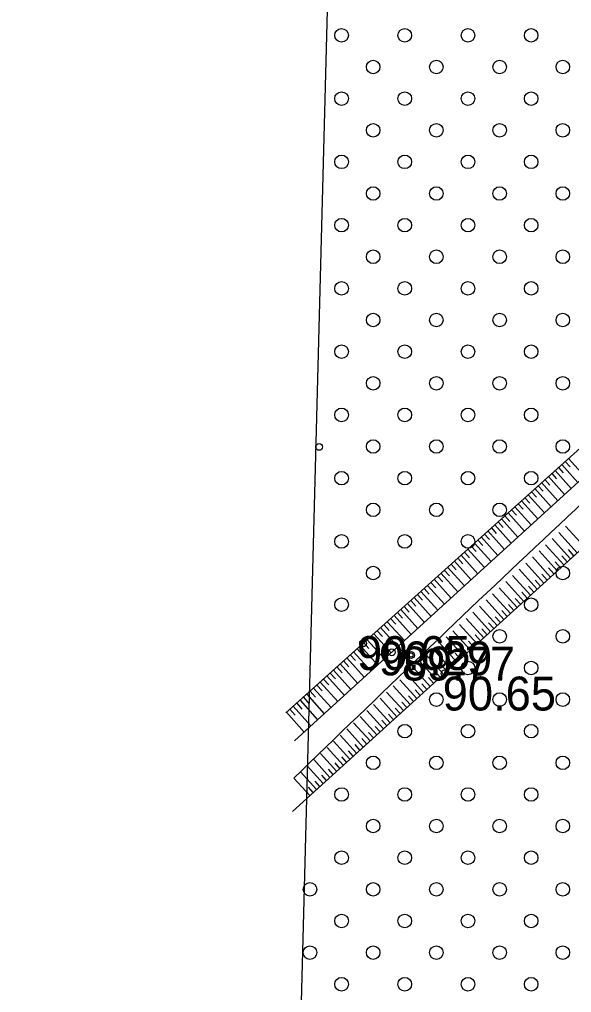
# Model space of a CAD drawing. Extents: x 316000 to 728450, y 314368 to 726000.
# Drawn here: x 725524.8 to 725586, y 315450.6 to 315558.3 of the extents above; entities that cross this region are included whole.
import ezdxf

# ---------------------------------------------------------------- set-up
doc = ezdxf.new("R2010")
doc.units = 0
for name, color, linetype in [('HIDG_ELEM_####_####_#', 7, 'Continuous'), ('HIDG_GRAV_####_####_#', 7, 'Continuous'), ('RAMI_UZMR_####_####_#', 7, 'Continuous'), ('RELJ_AATZ_####_TKST_#', 7, 'Continuous'), ('RELJ_ELEM_####_####_#', 7, 'Continuous'), ('RELJ_NOGA_####_####_#', 7, 'Continuous'), ('TERT_ELEM_####_####_#', 7, 'Continuous')]:
    doc.layers.add(name, color=color, linetype=linetype)

msp = doc.modelspace()

# ---------------------------------------------------------------- linework, layer by layer
at = {"layer": 'HIDG_ELEM_####_####_#'}
msp.add_circle((725568.19, 315487.93), 0.225, dxfattribs=at)
at = {"layer": 'HIDG_GRAV_####_####_#'}
msp.add_line((725611.33, 315529.51), (725555.29, 315478.43), dxfattribs=at)
msp.add_spline([(725741.16, 315628.11), (725732.01, 315633.48), (725729.37, 315630.94), (725612.67, 315527.51), (725555.21, 315474.31)], degree=3, dxfattribs=at)
at = {"layer": 'RAMI_UZMR_####_####_#'}
msp.add_lwpolyline([(727254.69, 315085.95), (727002.7, 315002.84), (726508.21, 314868.03), (726416.7, 314837.05), (725982.38, 314530.96), (725916.44, 314513.26), (725799.16, 314549.2), (725735.9, 314623.63), (725701.82, 314711.1), (725697.25, 315112.64), (725659.91, 315163.35), (725614.81, 315211.65), (725561.8, 315231.45), (725500.09, 315274.21), (725474.77, 315308.26), (725484.26, 315374.77), (725505.03, 315405.04), (725554.87, 315404.25), (725559.14, 315567.14), (725558.67, 315591.68), (725662, 315676.73), (726089.69, 315915.19)], dxfattribs=at)
at = {"layer": 'RELJ_ELEM_####_####_#'}
for centre in [(725558.01, 315510.96), (725562.88, 315489.21), (725566.06, 315488.23), (725568.19, 315487.93), (725571.91, 315485.9)]:
    msp.add_circle(centre, 0.375, dxfattribs=at)
at = {"layer": 'RELJ_NOGA_####_####_#'}
for p, q in [((725610.17, 315531.75), (725554.34, 315481.53)), ((725614.75, 315524.79), (725555.07, 315470.62)), ((725585.26, 315509.35), (725585.8, 315508.75)), ((725585.64, 315509.68), (725587.41, 315507.71)), ((725584.15, 315508.34), (725585.94, 315506.36)), ((725584.52, 315508.68), (725585.06, 315508.08)), ((725584.89, 315509.01), (725586.67, 315507.03)), ((725582.66, 315507.01), (725584.46, 315505.01)), ((725583.03, 315507.34), (725583.57, 315506.74)), ((725583.4, 315507.68), (725585.2, 315505.68)), ((725583.78, 315508.01), (725584.31, 315507.41)), ((725581.55, 315506), (725582.09, 315505.4)), ((725581.92, 315506.34), (725583.72, 315504.34)), ((725582.29, 315506.67), (725582.83, 315506.07)), ((725580.43, 315505), (725582.24, 315502.99)), ((725580.8, 315505.33), (725581.34, 315504.73)), ((725581.17, 315505.67), (725582.98, 315503.66)), ((725579.32, 315504), (725579.86, 315503.39)), ((725579.69, 315504.33), (725581.5, 315502.32)), ((725580.06, 315504.67), (725580.6, 315504.06)), ((725577.83, 315502.66), (725578.38, 315502.05)), ((725578.2, 315502.99), (725580.02, 315500.97)), ((725578.57, 315503.33), (725579.12, 315502.72)), ((725578.94, 315503.66), (725580.76, 315501.64)), ((725576.71, 315501.66), (725578.54, 315499.62)), ((725577.09, 315501.99), (725577.63, 315501.38)), ((725577.46, 315502.33), (725579.28, 315500.3)), ((725587.35, 315499.92), (725585.31, 315502.17)), ((725575.6, 315500.65), (725576.15, 315500.04)), ((725575.97, 315500.99), (725577.81, 315498.95)), ((725576.34, 315501.32), (725576.89, 315500.71)), ((725585.87, 315498.58), (725583.84, 315500.81)), ((725586.61, 315499.25), (725584.57, 315501.49)), ((725574.48, 315499.65), (725576.33, 315497.6)), ((725574.86, 315499.98), (725575.41, 315499.37)), ((725575.23, 315500.32), (725577.07, 315498.27)), ((725584.39, 315497.23), (725582.37, 315499.45)), ((725585.13, 315497.91), (725583.1, 315500.13)), ((725586.24, 315498.91), (725585.63, 315499.59)), ((725573.37, 315498.65), (725573.92, 315498.03)), ((725573.74, 315498.98), (725575.59, 315496.93)), ((725574.11, 315499.32), (725574.67, 315498.7)), ((725583.64, 315496.56), (725581.64, 315498.78)), ((725585.5, 315498.24), (725584.89, 315498.91)), ((725571.88, 315497.31), (725572.44, 315496.69)), ((725572.25, 315497.64), (725574.11, 315495.58)), ((725572.62, 315497.98), (725573.18, 315497.36)), ((725573, 315498.31), (725574.85, 315496.25)), ((725582.16, 315495.22), (725580.17, 315497.42)), ((725582.9, 315495.89), (725580.9, 315498.1)), ((725584.02, 315496.9), (725583.41, 315497.56)), ((725584.76, 315497.57), (725584.15, 315498.24)), ((725570.77, 315496.31), (725572.63, 315494.23)), ((725571.14, 315496.64), (725571.7, 315496.02)), ((725571.51, 315496.97), (725573.37, 315494.91)), ((725581.42, 315494.55), (725579.44, 315496.74)), ((725582.53, 315495.55), (725581.93, 315496.21)), ((725583.27, 315496.23), (725582.67, 315496.89)), ((725569.65, 315495.3), (725570.21, 315494.68)), ((725570.02, 315495.64), (725571.89, 315493.56)), ((725570.39, 315495.97), (725570.95, 315495.35)), ((725579.94, 315493.2), (725577.97, 315495.38)), ((725580.68, 315493.87), (725578.7, 315496.06)), ((725581.79, 315494.88), (725581.2, 315495.54)), ((725568.54, 315494.3), (725570.41, 315492.21)), ((725568.91, 315494.63), (725569.47, 315494.01)), ((725569.28, 315494.97), (725571.15, 315492.89)), ((725578.46, 315491.86), (725576.5, 315494.02)), ((725579.2, 315492.53), (725577.23, 315494.7)), ((725580.31, 315493.54), (725579.72, 315494.19)), ((725581.05, 315494.21), (725580.46, 315494.87)), ((725567.05, 315492.96), (725568.94, 315490.86)), ((725567.42, 315493.3), (725567.99, 315492.67)), ((725567.79, 315493.63), (725569.68, 315491.54)), ((725568.16, 315493.97), (725568.73, 315493.34)), ((725577.72, 315491.19), (725575.77, 315493.34)), ((725579.57, 315492.87), (725578.98, 315493.52)), ((725565.93, 315491.96), (725566.5, 315491.33)), ((725566.31, 315492.29), (725568.2, 315490.19)), ((725566.68, 315492.63), (725567.24, 315492)), ((725576.24, 315489.84), (725574.3, 315491.98)), ((725576.98, 315490.51), (725575.03, 315492.66)), ((725578.09, 315491.52), (725577.5, 315492.17)), ((725578.83, 315492.19), (725578.24, 315492.84)), ((725564.82, 315490.96), (725566.72, 315488.84)), ((725565.19, 315491.29), (725565.76, 315490.66)), ((725565.56, 315491.62), (725567.46, 315489.52)), ((725575.5, 315489.17), (725573.56, 315491.3)), ((725576.61, 315490.18), (725576.03, 315490.82)), ((725577.35, 315490.85), (725576.77, 315491.49)), ((725563.7, 315489.95), (725564.28, 315489.32)), ((725564.08, 315490.29), (725565.98, 315488.17)), ((725564.45, 315490.62), (725565.02, 315489.99)), ((725574.02, 315487.83), (725572.1, 315489.94)), ((725574.76, 315488.5), (725572.83, 315490.62)), ((725575.87, 315489.51), (725575.29, 315490.15)), ((725562.59, 315488.95), (725564.5, 315486.82)), ((725562.96, 315489.28), (725563.53, 315488.65)), ((725563.33, 315489.62), (725565.24, 315487.5)), ((725573.28, 315487.15), (725571.36, 315489.26)), ((725574.39, 315488.16), (725573.81, 315488.8)), ((725575.13, 315488.83), (725574.55, 315489.47)), ((725561.1, 315487.61), (725563.02, 315485.48)), ((725561.47, 315487.95), (725562.05, 315487.31)), ((725561.84, 315488.28), (725563.76, 315486.15)), ((725562.22, 315488.61), (725562.79, 315487.98)), ((725571.8, 315485.81), (725569.9, 315487.9)), ((725572.54, 315486.48), (725570.63, 315488.58)), ((725573.65, 315487.49), (725573.07, 315488.12)), ((725559.99, 315486.61), (725560.56, 315485.97)), ((725560.36, 315486.94), (725562.28, 315484.8)), ((725560.73, 315487.28), (725561.31, 315486.64)), ((725570.32, 315484.46), (725568.43, 315486.54)), ((725571.06, 315485.14), (725569.16, 315487.22)), ((725572.17, 315486.14), (725571.6, 315486.77)), ((725572.91, 315486.82), (725572.33, 315487.45)), ((725558.87, 315485.61), (725560.81, 315483.45)), ((725559.24, 315485.94), (725559.82, 315485.3)), ((725559.61, 315486.27), (725561.54, 315484.13)), ((725569.58, 315483.79), (725567.69, 315485.87)), ((725570.69, 315484.8), (725570.12, 315485.43)), ((725571.43, 315485.47), (725570.86, 315486.1)), ((725557.76, 315484.6), (725558.34, 315483.95)), ((725558.13, 315484.94), (725560.07, 315482.78)), ((725558.5, 315485.27), (725559.08, 315484.63)), ((725568.09, 315482.45), (725566.23, 315484.51)), ((725568.84, 315483.12), (725566.96, 315485.19)), ((725569.95, 315484.13), (725569.38, 315484.75)), ((725556.27, 315483.26), (725556.85, 315482.61)), ((725556.64, 315483.6), (725558.59, 315481.43)), ((725557.01, 315483.93), (725557.6, 315483.28)), ((725557.38, 315484.27), (725559.33, 315482.11)), ((725567.35, 315481.78), (725565.49, 315483.83)), ((725568.47, 315482.78), (725567.9, 315483.4)), ((725569.21, 315483.46), (725568.64, 315484.08)), ((725555.15, 315482.26), (725557.11, 315480.09)), ((725555.53, 315482.6), (725556.11, 315481.94)), ((725555.9, 315482.93), (725557.85, 315480.76)), ((725565.87, 315480.43), (725564.03, 315482.47)), ((725566.61, 315481.1), (725564.76, 315483.15)), ((725567.72, 315482.11), (725567.17, 315482.73)), ((725554.41, 315481.59), (725556.37, 315479.41)), ((725554.78, 315481.93), (725555.37, 315481.27)), ((725564.39, 315479.09), (725562.56, 315481.11)), ((725565.13, 315479.76), (725563.29, 315481.79)), ((725566.24, 315480.77), (725565.69, 315481.38)), ((725566.98, 315481.44), (725566.43, 315482.05)), ((725563.65, 315478.42), (725561.82, 315480.43)), ((725564.76, 315479.42), (725564.21, 315480.03)), ((725565.5, 315480.1), (725564.95, 315480.71)), ((725562.17, 315477.07), (725560.36, 315479.07)), ((725562.91, 315477.74), (725561.09, 315479.75)), ((725564.02, 315478.75), (725563.47, 315479.36)), ((725561.43, 315476.4), (725559.62, 315478.39)), ((725562.54, 315477.41), (725562, 315478.01)), ((725563.28, 315478.08), (725562.73, 315478.68)), ((725559.95, 315475.06), (725558.16, 315477.03)), ((725560.69, 315475.73), (725558.89, 315477.71)), ((725561.8, 315476.74), (725561.26, 315477.33)), ((725559.21, 315474.38), (725557.42, 315476.35)), ((725560.32, 315475.39), (725559.78, 315475.99)), ((725561.06, 315476.06), (725560.52, 315476.66)), ((725557.73, 315473.04), (725555.95, 315474.99)), ((725558.47, 315473.71), (725556.69, 315475.67)), ((725558.84, 315474.05), (725558.3, 315474.64)), ((725559.58, 315474.72), (725559.04, 315475.31)), ((725556.99, 315472.37), (725555.22, 315474.31)), ((725558.1, 315473.38), (725557.57, 315473.96)), ((725557.36, 315472.7), (725556.83, 315473.29)), ((725556.25, 315471.7), (725556.25, 315471.7)), ((725556.62, 315472.03), (725556.62, 315472.03)), ((725555.14, 315470.69), (725555.14, 315470.69)), ((725555.51, 315471.02), (725555.51, 315471.02)), ((725555.88, 315471.36), (725555.88, 315471.36))]:
    msp.add_line(p, q, dxfattribs=at)
at = {"layer": 'TERT_ELEM_####_####_#'}
for centre in [(725560.5, 315556.5), (725567.5, 315556.5), (725574.5, 315556.5), (725581.5, 315556.5), (725564, 315553), (725571, 315553), (725578, 315553), (725585, 315553), (725560.5, 315549.5), (725567.5, 315549.5), (725574.5, 315549.5), (725581.5, 315549.5), (725564, 315546), (725571, 315546), (725578, 315546), (725585, 315546), (725560.5, 315542.5), (725567.5, 315542.5), (725574.5, 315542.5), (725581.5, 315542.5), (725564, 315539), (725571, 315539), (725578, 315539), (725585, 315539), (725560.5, 315535.5), (725567.5, 315535.5), (725574.5, 315535.5), (725581.5, 315535.5), (725564, 315532), (725571, 315532), (725578, 315532), (725585, 315532), (725560.5, 315528.5), (725567.5, 315528.5), (725574.5, 315528.5), (725581.5, 315528.5), (725564, 315525), (725571, 315525), (725578, 315525), (725585, 315525), (725560.5, 315521.5), (725567.5, 315521.5), (725574.5, 315521.5), (725581.5, 315521.5), (725564, 315518), (725571, 315518), (725578, 315518), (725585, 315518), (725560.5, 315514.5), (725567.5, 315514.5), (725574.5, 315514.5), (725581.5, 315514.5), (725564, 315511), (725571, 315511), (725578, 315511), (725585, 315511), (725560.5, 315507.5), (725567.5, 315507.5), (725574.5, 315507.5), (725581.5, 315507.5), (725564, 315504), (725571, 315504), (725578, 315504), (725560.5, 315500.5), (725567.5, 315500.5), (725574.5, 315500.5), (725564, 315497), (725585, 315497), (725560.5, 315493.5), (725581.5, 315493.5), (725578, 315490), (725585, 315490), (725574.5, 315486.5), (725581.5, 315486.5), (725571, 315483), (725578, 315483), (725585, 315483), (725567.5, 315479.5), (725574.5, 315479.5), (725581.5, 315479.5), (725564, 315476), (725571, 315476), (725578, 315476), (725585, 315476), (725560.5, 315472.5), (725567.5, 315472.5), (725574.5, 315472.5), (725581.5, 315472.5), (725564, 315469), (725571, 315469), (725578, 315469), (725585, 315469), (725560.5, 315465.5), (725567.5, 315465.5), (725574.5, 315465.5), (725581.5, 315465.5), (725557, 315462), (725564, 315462), (725571, 315462), (725578, 315462), (725585, 315462), (725560.5, 315458.5), (725567.5, 315458.5), (725574.5, 315458.5), (725581.5, 315458.5), (725557, 315455), (725564, 315455), (725571, 315455), (725578, 315455), (725585, 315455), (725560.5, 315451.5), (725567.5, 315451.5), (725574.5, 315451.5), (725581.5, 315451.5)]:
    msp.add_circle(centre, 0.75, dxfattribs=at)

# ---------------------------------------------------------------- texts
at = {"layer": 'RELJ_AATZ_####_TKST_#'}
for s, p in [('90.65', (725562.21, 315486.27)), ('90.29', (725564.63, 315485.68)), ('89.77', (725567.17, 315485.11)), ('90.65', (725571.7, 315481.79))]:
    msp.add_text(s, height=3.75, dxfattribs=at).set_placement(p)

doc.saveas('drawing.dxf')
